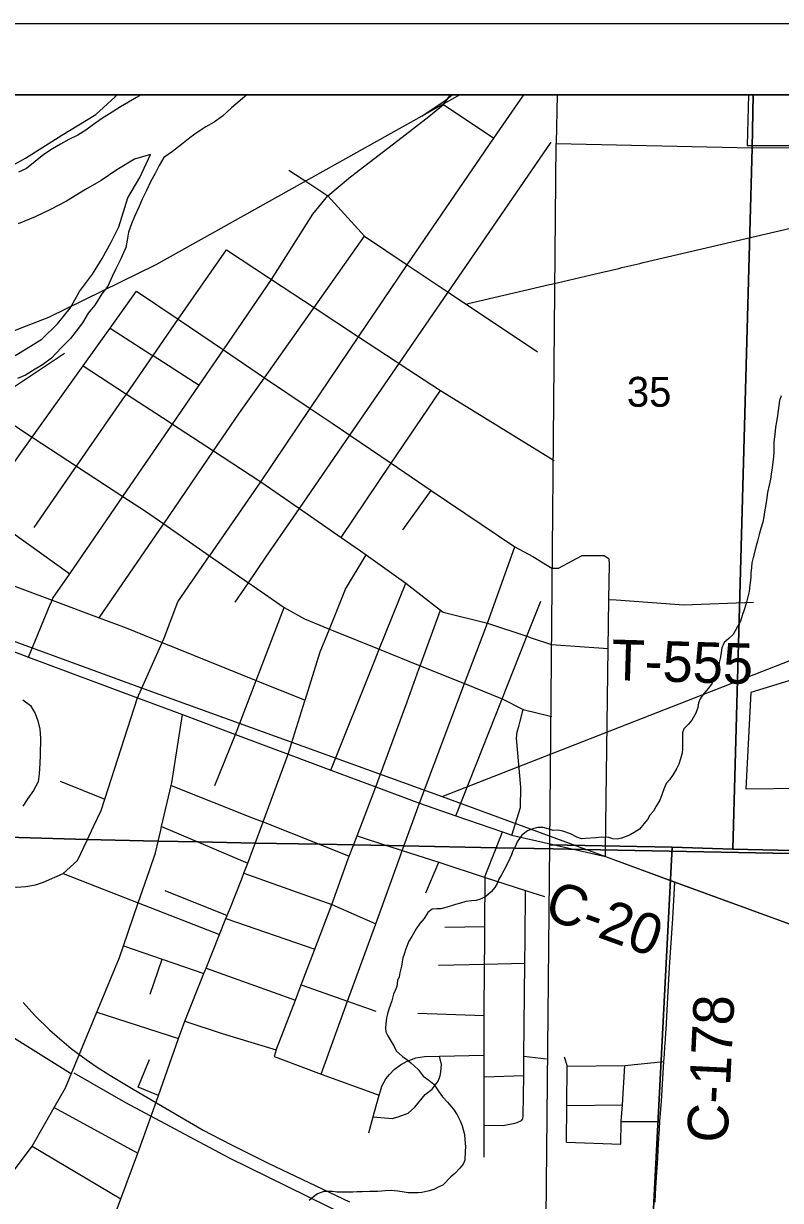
# Model space of a CAD drawing. Extents: x 36.7 to 70.7, y 0 to 22.
# Drawn here: x 39.365 to 40.424, y 19.349 to 20.997 of the extents above; entities that cross this region are included whole.
import ezdxf

# ---------------------------------------------------------------- set-up
doc = ezdxf.new("R2010")
doc.units = 0
for name, color, linetype in [('Default', 7, 'Continuous'), ('GM_X_City_Street', 7, 'Continuous'), ('GM_X_County_Road', 7, 'Continuous'), ('GM_X_County_Road_Text', 7, 'Continuous'), ('GM_X_Major_River', 7, 'Continuous'), ('GM_X_Minor_River', 7, 'Continuous'), ('GM_X_Rail_Line', 7, 'Continuous'), ('GM_X_Section', 7, 'Continuous'), ('GM_X_Section_Text', 7, 'Continuous'), ('GM_X_Township_Road', 7, 'Continuous'), ('GM_X_Township_Road_Text', 7, 'Continuous'), ('SH_Data', 7, 'Continuous')]:
    doc.layers.add(name, color=color, linetype=linetype)

msp = doc.modelspace()

# ---------------------------------------------------------------- linework, layer by layer
at = {"layer": 'Default'}
for points in [[(40.3859, 20.8969), (40.1114, 20.8969), (40.1102, 20.8288), (40.3846, 20.8226)], [(41.3719, 20.8969), (40.3859, 20.8969), (40.3846, 20.8226), (41.3712, 20.8297)]]:
    msp.add_lwpolyline(points, close=True, dxfattribs=at)
for points in [[(40.895, 20.8969), (40.3795, 20.8969), (40.3778, 20.8261), (40.5438, 20.8262)], [(40.5967, 20.1257), (40.3825, 20.0602), (40.3755, 19.9253), (40.4538, 19.9259)]]:
    msp.add_lwpolyline(points, dxfattribs=at)
at = {"layer": 'GM_X_City_Street'}
for p, q in [((39.9525, 20.8834), (40.0231, 20.8366)), ((39.4858, 20.5702), (39.5439, 20.533)), ((39.8955, 20.2878), (39.9353, 20.3431)), ((40.0139, 20.1571), (40.0523, 20.2638)), ((39.6325, 19.9296), (39.6611, 20.0013)), ((39.416, 19.936), (39.4784, 19.9107)), ((39.5711, 19.9298), (39.6862, 19.8841)), ((39.9278, 19.7794), (39.946, 19.8222)), ((39.6731, 19.8068), (39.7963, 19.7629)), ((39.5624, 19.7828), (39.6497, 19.7478)), ((39.7963, 19.7629), (39.8576, 19.7361)), ((39.648, 19.7435), (39.7724, 19.7003)), ((39.9544, 19.7312), (40.0104, 19.7324)), ((39.542, 19.6376), (39.5585, 19.6867)), ((39.6201, 19.6741), (39.7451, 19.6289)), ((39.467, 19.6121), (39.5816, 19.5752)), ((39.9167, 19.611), (40.0095, 19.6077)), ((39.7183, 19.5594), (39.7218, 19.5687)), ((40.0651, 19.5508), (40.0967, 19.547)), ((39.7813, 19.5253), (39.8624, 19.4958)), ((40.0093, 19.5215), (40.0648, 19.5238)), ((39.4076, 19.4786), (39.5245, 19.4148)), ((39.3768, 19.4246), (39.5009, 19.3508))]:
    msp.add_line(p, q, dxfattribs=at)
for points in [[(39.0756, 20.5973), (39.1222, 20.6178), (39.146, 20.6331), (39.1885, 20.674), (39.2532, 20.7387), (39.3059, 20.7744), (39.3672, 20.8085), (39.4182, 20.8408), (39.4659, 20.8697), (39.4929, 20.8944), (39.495, 20.8969)], [(39.7906, 20.7554), (39.8222, 20.7823), (39.8948, 20.838), (39.9321, 20.8665), (39.9525, 20.8834), (39.9624, 20.8969)], [(39.6608, 20.1866), (39.6794, 20.2138), (39.7039, 20.2495), (39.7508, 20.3177), (39.8212, 20.4203), (39.8904, 20.521), (39.9588, 20.6206), (39.9682, 20.6343), (40.1031, 20.8307)], [(39.7359, 20.7914), (39.7639, 20.7735), (39.7906, 20.7554)], [(39.4705, 20.1645), (39.5552, 20.2882), (39.5608, 20.2963), (39.6306, 20.3983), (39.667, 20.4515), (39.702, 20.5009), (39.7715, 20.5992), (39.842, 20.6989)], [(39.3793, 20.2913), (39.4354, 20.3723), (39.4387, 20.3771), (39.5027, 20.4695), (39.5086, 20.478), (39.5459, 20.5318), (39.5811, 20.5827), (39.6486, 20.6802)], [(39.6486, 20.6802), (39.7077, 20.6413), (39.7119, 20.6385), (39.7715, 20.5992), (39.8336, 20.5583), (39.8849, 20.5246)], [(39.2718, 20.2665), (39.305, 20.3151), (39.3385, 20.3641), (39.3767, 20.4176), (39.4481, 20.5176), (39.4858, 20.5702), (39.5229, 20.622)], [(39.5229, 20.622), (39.5811, 20.5827), (39.6443, 20.5399), (39.702, 20.5009), (39.7658, 20.4578), (39.7965, 20.4371), (39.8212, 20.4203), (39.8793, 20.381), (39.9353, 20.3431), (40.0523, 20.2638), (40.0774, 20.2506), (40.1043, 20.2343), (40.1135, 20.2343), (40.1455, 20.2515)], [(39.9847, 20.6033), (40.033, 20.5712), (40.0842, 20.5373)], [(39.3387, 20.4754), (39.3491, 20.4866), (39.4218, 20.5351)], [(39.5439, 20.533), (39.5459, 20.5318), (39.6104, 20.4905)], [(39.8849, 20.5246), (39.8904, 20.521), (39.9482, 20.4829), (40.1076, 20.3851)], [(39.4481, 20.5176), (39.5086, 20.478), (39.5669, 20.44), (39.573, 20.436), (39.6306, 20.3983), (39.6941, 20.3568), (39.6966, 20.3552)], [(39.8092, 20.2773), (39.8793, 20.381), (39.9482, 20.4829)], [(39.3197, 20.4548), (39.3767, 20.4176), (39.3783, 20.4166)], [(39.3783, 20.4166), (39.4387, 20.3771), (39.5036, 20.3347), (39.5355, 20.3139), (39.5608, 20.2963), (39.6251, 20.2516), (39.6794, 20.2138), (39.685, 20.2099), (39.7293, 20.179), (39.7577, 20.163), (39.7928, 20.1488), (39.7976, 20.1469), (39.8626, 20.1206), (39.9199, 20.0974), (39.9819, 20.0724), (40.0324, 20.052), (40.0346, 20.0509), (40.0638, 20.0361), (40.1042, 20.0263)], [(39.2001, 20.39), (39.241, 20.3608), (39.2432, 20.3592), (39.305, 20.3151), (39.3065, 20.314), (39.4292, 20.2264)], [(39.1805, 20.273), (39.2568, 20.2444), (39.4045, 20.1892), (39.4705, 20.1645), (39.5083, 20.1504), (39.5587, 20.13), (39.6901, 20.0769), (39.6928, 20.0758), (39.7587, 20.0492)], [(39.7946, 19.9513), (39.8569, 20.1063), (39.8626, 20.1206), (39.8997, 20.2129)], [(39.6611, 20.0013), (39.6901, 20.0769), (39.7293, 20.179)], [(39.9699, 19.8873), (40.0346, 20.0509), (40.0664, 20.1315), (40.0693, 20.1387), (40.0887, 20.1879)], [(39.8577, 19.9277), (39.9014, 20.0469), (39.9181, 20.0927), (39.9199, 20.0974), (39.9484, 20.1753)], [(40.0139, 20.1571), (40.0693, 20.1387), (40.0751, 20.1367), (40.1037, 20.1272)], [(39.2277, 19.1683), (39.2656, 19.2467), (39.3144, 19.3333), (39.3351, 19.369), (39.3768, 19.4246), (39.4076, 19.4786), (39.4235, 19.5064), (39.467, 19.6121), (39.474, 19.629), (39.4987, 19.6889), (39.5044, 19.7053), (39.5252, 19.7656), (39.5409, 19.8109), (39.5494, 19.8356), (39.5531, 19.8514), (39.5567, 19.867), (39.5579, 19.8722), (39.5711, 19.9298), (39.572, 19.9335), (39.5869, 20.029)], [(40.048, 19.8604), (40.0601, 19.899), (40.0606, 19.9272), (40.0546, 19.996), (40.0557, 20.0047), (40.0579, 20.0123), (40.06, 20.0199), (40.0638, 20.0361)], [(39.7218, 19.5687), (39.7451, 19.6289), (39.7534, 19.6505), (39.7724, 19.7003), (39.7963, 19.7629), (39.8192, 19.8271), (39.8205, 19.8308), (39.8263, 19.846), (39.8315, 19.8593), (39.8577, 19.9277)], [(39.6862, 19.8841), (39.6999, 19.8787), (39.78, 19.8469), (39.8205, 19.8308)], [(39.5579, 19.8722), (39.6097, 19.8502), (39.6785, 19.8211)], [(40.0094, 19.4093), (40.0094, 19.4542), (40.0093, 19.5215), (40.0093, 19.5519), (40.0093, 19.5915), (40.0095, 19.6077), (40.01, 19.6796), (40.0102, 19.7062), (40.0104, 19.7324), (40.011, 19.8011), (40.011, 19.8034), (40.0263, 19.842), (40.0353, 19.8648)], [(39.8315, 19.8593), (39.8757, 19.845), (39.8877, 19.8411), (39.8948, 19.8388), (39.946, 19.8222), (40.011, 19.8011), (40.0674, 19.7828), (40.0938, 19.7742)], [(40.0094, 19.4542), (40.036, 19.4534), (40.0523, 19.4566), (40.0556, 19.4577), (40.0615, 19.4606), (40.0634, 19.463), (40.0642, 19.4664), (40.0648, 19.5238), (40.0651, 19.5508), (40.0664, 19.6811), (40.0667, 19.7136), (40.0674, 19.7828)], [(39.5044, 19.7053), (39.5585, 19.6867), (39.6171, 19.6666)], [(39.9455, 19.6779), (40.01, 19.6796), (40.0664, 19.6811)], [(39.7534, 19.6505), (39.8183, 19.6276), (39.8576, 19.6137)], [(39.848, 19.4432), (39.854, 19.4658), (39.8559, 19.4729), (39.8624, 19.4958), (39.8646, 19.5034), (39.866, 19.5087), (39.8718, 19.5187), (39.8768, 19.5251), (39.8834, 19.5318), (39.8925, 19.5387), (39.9015, 19.5437), (39.9139, 19.5482), (39.9258, 19.5502), (39.9467, 19.5507), (40.0093, 19.5519)], [(39.854, 19.4658), (39.8805, 19.4632), (39.8888, 19.4658), (39.9032, 19.471), (39.9123, 19.4793), (39.9267, 19.4968), (39.9367, 19.5046), (39.9448, 19.5158), (39.9478, 19.523), (39.9489, 19.5286), (39.9495, 19.5388), (39.9467, 19.5507)], [(39.5534, 19.4954), (39.5249, 19.5073), (39.5268, 19.5119), (39.5411, 19.5459)]]:
    msp.add_lwpolyline(points, dxfattribs=at)
at = {"layer": 'GM_X_County_Road'}
for p, q in [((40.1036, 19.8477), (40.1319, 19.8412)), ((39.4202, 19.8065), (39.4677, 19.7879)), ((40.2632, 19.5736), (40.2639, 19.5838)), ((40.2624, 19.5635), (40.2632, 19.5736)), ((40.261, 19.5432), (40.2617, 19.5533)), ((40.2617, 19.5533), (40.2624, 19.5635)), ((39.7242, 19.5471), (39.7813, 19.5253)), ((40.2548, 19.4488), (40.2554, 19.4591)), ((40.2536, 19.4283), (40.2548, 19.4488)), ((40.2525, 19.4078), (40.2536, 19.4283))]:
    msp.add_line(p, q, dxfattribs=at)
for points in [[(39.9014, 20.6589), (40.0231, 20.8366), (40.0649, 20.8969)], [(39.4027, 20.1848), (39.4045, 20.1892), (39.4058, 20.1923), (39.4292, 20.2264), (39.5036, 20.3347), (39.573, 20.436), (39.6104, 20.4905), (39.6443, 20.5399), (39.7119, 20.6385), (39.7697, 20.73), (39.7906, 20.7554)], [(39.7906, 20.7554), (39.842, 20.6989), (39.9014, 20.6589)], [(40.2321, 20.662), (40.5482, 20.7359), (40.5572, 20.738)], [(39.6257, 20.2524), (39.6966, 20.3552), (39.7658, 20.4578), (39.8336, 20.5583), (39.9014, 20.6589)], [(39.9014, 20.6589), (39.9588, 20.6206), (39.9847, 20.6033), (39.9858, 20.604)], [(40.163, 20.6458), (40.198, 20.654), (40.202, 20.655)], [(40.202, 20.655), (40.2272, 20.6608), (40.2321, 20.662)], [(40.1037, 20.632), (40.1591, 20.6449), (40.163, 20.6458)], [(39.9858, 20.604), (39.9869, 20.6047), (40.1007, 20.6313), (40.1037, 20.632)], [(39.6966, 20.3552), (39.7508, 20.3177), (39.8092, 20.2773), (39.8365, 20.2583)], [(39.5609, 20.135), (39.5621, 20.1377), (39.5804, 20.1868), (39.6251, 20.2516), (39.6257, 20.2524)], [(39.7352, 19.9735), (39.7585, 20.0484), (39.7587, 20.0492), (39.7797, 20.1168), (39.7928, 20.1488), (39.8155, 20.2047), (39.8444, 20.2529)], [(39.8365, 20.2583), (39.8444, 20.2529), (39.877, 20.2293), (39.8997, 20.2129), (39.9484, 20.1753), (39.952, 20.1725), (40.0139, 20.1571)], [(39.1685, 20.1856), (39.2162, 20.1677), (39.299, 20.1368), (39.3715, 20.1096)], [(39.3715, 20.1096), (39.402, 20.1831), (39.4027, 20.1848)], [(39.9187, 19.9049), (39.9819, 20.0724), (40.0139, 20.1571)], [(39.4779, 19.9092), (39.4784, 19.9107), (39.5243, 20.0525), (39.5587, 20.13), (39.5609, 20.135)], [(39.3715, 20.1096), (39.5243, 20.0525), (39.5869, 20.029), (39.6611, 20.0013), (39.7352, 19.9735), (39.7946, 19.9513), (39.8577, 19.9277), (39.9187, 19.9049), (39.9699, 19.8873), (40.0353, 19.8648), (40.048, 19.8604), (40.1036, 19.8477)], [(39.6863, 19.8423), (39.6887, 19.8487), (39.6999, 19.8787), (39.7352, 19.9735)], [(39.4626, 19.8723), (39.4732, 19.8949), (39.4779, 19.9092)], [(39.8918, 19.8305), (39.8948, 19.8388), (39.8969, 19.8446), (39.9187, 19.9049)], [(39.4202, 19.8065), (39.4402, 19.8248), (39.4536, 19.8533), (39.4626, 19.8723)], [(39.1936, 19.8465), (39.3308, 19.7914), (39.3464, 19.7876), (39.355, 19.7873), (39.3678, 19.7882), (39.3812, 19.7907), (39.3925, 19.7942), (39.4202, 19.8065)], [(39.6541, 19.7587), (39.6702, 19.799), (39.6731, 19.8068), (39.6785, 19.8211), (39.6863, 19.8423)], [(39.7813, 19.5253), (39.8183, 19.6276), (39.8576, 19.7361), (39.8918, 19.8305)], [(40.1319, 19.8412), (40.1791, 19.8304), (40.2761, 19.7943)], [(39.4677, 19.7879), (39.5252, 19.7656), (39.639, 19.7212)], [(40.2661, 19.624), (40.2689, 19.6751), (40.2735, 19.7434), (40.2761, 19.7943)], [(40.2761, 19.7943), (40.6359, 19.663), (40.6688, 19.6508)], [(39.5904, 19.5999), (39.6171, 19.6666), (39.6201, 19.6741), (39.639, 19.7212), (39.648, 19.7435), (39.6497, 19.7478), (39.6515, 19.7523), (39.6541, 19.7587)], [(40.2639, 19.5838), (40.2642, 19.5878), (40.2661, 19.624)], [(39.4349, 19.1716), (39.5009, 19.3508), (39.5245, 19.4148), (39.5326, 19.4368), (39.5534, 19.4954), (39.5816, 19.5752), (39.5904, 19.5999)], [(39.5904, 19.5999), (39.6428, 19.5822), (39.7183, 19.5594), (39.7156, 19.5504), (39.7242, 19.5471)], [(40.2554, 19.4591), (40.2578, 19.4874), (40.261, 19.5432)], [(40.2499, 19.3665), (40.2513, 19.3873), (40.2525, 19.4078)], [(40.2487, 19.3463), (40.2492, 19.3572), (40.2499, 19.3665)]]:
    msp.add_lwpolyline(points, dxfattribs=at)
at = {"layer": 'GM_X_Major_River'}
for points in [[(39.6773, 20.8969), (39.6559, 20.8789), (39.6433, 20.8673), (39.6314, 20.8587), (39.62, 20.8524), (39.6077, 20.8442), (39.5974, 20.8367), (39.5859, 20.8277), (39.5733, 20.8176), (39.5611, 20.8094), (39.5545, 20.798), (39.549, 20.7867), (39.5428, 20.7761), (39.5366, 20.7633), (39.5308, 20.7508), (39.5261, 20.7399), (39.5199, 20.7267), (39.5156, 20.7164), (39.5113, 20.7047), (39.5097, 20.6937), (39.5076, 20.6831), (39.501, 20.6676), (39.494, 20.6533), (39.4886, 20.6427), (39.4828, 20.6291), (39.4743, 20.6182), (39.4643, 20.6027), (39.455, 20.5914), (39.4473, 20.5779), (39.4384, 20.5662), (39.4303, 20.556), (39.4173, 20.5429), (39.4038, 20.5282), (39.3912, 20.5189), (39.3809, 20.5129), (39.3675, 20.5043), (39.3561, 20.4999)], [(39.5291, 20.8969), (39.5226, 20.8933), (39.5115, 20.8869), (39.5004, 20.8802), (39.4886, 20.8728), (39.4737, 20.8634), (39.4626, 20.8556), (39.4519, 20.8477), (39.4404, 20.8406), (39.4278, 20.8343), (39.4164, 20.828), (39.4053, 20.8216), (39.3931, 20.8134), (39.3686, 20.7939), (39.3575, 20.7887)], [(39.5421, 20.8137), (39.5197, 20.8071), (39.4952, 20.7918), (39.4731, 20.7769), (39.4513, 20.7646), (39.4246, 20.7482), (39.4024, 20.7363), (39.3807, 20.7262), (39.357, 20.7162)], [(39.4981, 20.7121), (39.5108, 20.753), (39.5274, 20.7812), (39.5421, 20.8137)], [(39.3443, 20.527), (39.3683, 20.5415), (39.3901, 20.5549), (39.412, 20.5763), (39.4301, 20.5985), (39.4428, 20.6216), (39.4613, 20.6457), (39.4749, 20.6679), (39.4873, 20.6906), (39.4981, 20.7121)], [(39.3635, 20.0499), (39.3744, 20.0419), (39.3807, 20.0304), (39.3844, 20.0201), (39.3873, 20.0087), (39.3883, 19.9962), (39.388, 19.9722), (39.3872, 19.9605), (39.3866, 19.9461), (39.3853, 19.9351), (39.3784, 19.9226), (39.3707, 19.9113), (39.3637, 19.9008)]]:
    msp.add_lwpolyline(points, dxfattribs=at)
at = {"layer": 'GM_X_Minor_River'}
for points in [[(40.4252, 20.4755), (40.4228, 20.4691), (40.4208, 20.4551), (40.4199, 20.4479), (40.4187, 20.4392), (40.4171, 20.4316), (40.4162, 20.4214), (40.415, 20.4111), (40.4148, 20.3959), (40.4143, 20.3899), (40.4127, 20.3747), (40.411, 20.3656), (40.4102, 20.3588), (40.4082, 20.3505), (40.4058, 20.3399), (40.4045, 20.3292), (40.4037, 20.3232), (40.4017, 20.3129), (40.4009, 20.3061), (40.3993, 20.2985), (40.3965, 20.2895), (40.3945, 20.2811), (40.3921, 20.272), (40.3902, 20.2656), (40.3858, 20.249), (40.3842, 20.2418), (40.3834, 20.2349), (40.3829, 20.227), (40.3825, 20.2209), (40.3812, 20.2103), (40.3803, 20.2016), (40.3776, 20.1902), (40.376, 20.1845), (40.3736, 20.1758), (40.3705, 20.1679), (40.3681, 20.1599), (40.3638, 20.1513), (40.358, 20.1411), (40.3519, 20.1354), (40.3454, 20.1298), (40.3423, 20.1226), (40.3406, 20.1128), (40.3398, 20.1075), (40.3386, 20.1018), (40.337, 20.0923), (40.3354, 20.0855), (40.3311, 20.0783), (40.3284, 20.0731), (40.3234, 20.0659), (40.3169, 20.0584), (40.3119, 20.0512), (40.3095, 20.0455), (40.3083, 20.0391), (40.3059, 20.0312), (40.3001, 20.0213), (40.2955, 20.0157), (40.289, 20.0089), (40.287, 20.0033), (40.2869, 19.9866), (40.2872, 19.9809), (40.2867, 19.9756), (40.2844, 19.9672), (40.282, 19.9597), (40.2793, 19.954), (40.2739, 19.9453), (40.2688, 19.9378)], [(40.2688, 19.9378), (40.2642, 19.9325), (40.2607, 19.9246), (40.258, 19.9166), (40.2552, 19.9091), (40.2502, 19.9008), (40.2463, 19.8936), (40.2413, 19.888), (40.2382, 19.8819), (40.2329, 19.8759), (40.2267, 19.8688), (40.2195, 19.8639), (40.2137, 19.8606), (40.208, 19.8583), (40.2015, 19.8561), (40.1958, 19.8547), (40.1894, 19.8551), (40.1837, 19.8571), (40.1742, 19.8572), (40.1655, 19.8565), (40.1511, 19.8555), (40.1458, 19.8552), (40.139, 19.8572), (40.1303, 19.8622), (40.1193, 19.8657), (40.1125, 19.8673), (40.1061, 19.8666), (40.0989, 19.869), (40.0921, 19.871), (40.0845, 19.8707), (40.0788, 19.8696), (40.07, 19.8663), (40.062, 19.8603), (40.0558, 19.8509), (40.0535, 19.8448), (40.0496, 19.8384), (40.0476, 19.8327), (40.0453, 19.8274), (40.0414, 19.8195), (40.0368, 19.8108), (40.0337, 19.8044), (40.0298, 19.7984), (40.0275, 19.7927), (40.0244, 19.7867), (40.019, 19.7806), (40.0117, 19.7743), (40.0044, 19.7705), (39.998, 19.7687), (39.9919, 19.7684), (39.9839, 19.7673), (39.9763, 19.7651), (39.9691, 19.7629), (39.9577, 19.7593), (39.9489, 19.7571), (39.9432, 19.7572), (39.9368, 19.7565), (39.9306, 19.752), (39.9252, 19.7433), (39.9195, 19.7365), (39.9141, 19.729), (39.9083, 19.7184), (39.904, 19.7116), (39.8997, 19.7011), (39.8974, 19.6935), (39.8954, 19.6882), (39.8946, 19.6829), (39.8938, 19.6768), (39.8914, 19.6674), (39.8902, 19.6617), (39.8882, 19.6564), (39.887, 19.648), (39.885, 19.6428), (39.8827, 19.6375), (39.8803, 19.628), (39.876, 19.6167), (39.874, 19.6098), (39.8728, 19.6042), (39.8716, 19.5958), (39.8715, 19.5901), (39.8718, 19.5848), (39.8744, 19.5791), (39.8793, 19.5711), (39.883, 19.565), (39.886, 19.5581), (39.895, 19.5504), (39.901, 19.5462), (39.9066, 19.5412), (39.9168, 19.5319), (39.9239, 19.5228), (39.9321, 19.517), (39.9389, 19.5112), (39.9456, 19.5017), (39.9512, 19.4936), (39.958, 19.4863), (39.9666, 19.4764), (39.9718, 19.4683), (39.9759, 19.4603), (39.9785, 19.4531), (39.9821, 19.4409), (39.9824, 19.4341), (39.9831, 19.4238)], [(39.9831, 19.4238), (39.983, 19.4174), (39.9825, 19.4048), (39.9801, 19.3992), (39.9755, 19.3939), (39.9682, 19.3864), (39.9628, 19.3815), (39.9517, 19.3702), (39.9452, 19.3673), (39.9391, 19.3639), (39.9304, 19.3617), (39.922, 19.3599), (39.9167, 19.3592), (39.903, 19.3594), (39.8974, 19.3602), (39.8887, 19.3618), (39.8792, 19.3623), (39.8708, 19.362), (39.8606, 19.361), (39.8488, 19.3611), (39.8386, 19.3608), (39.8314, 19.3605), (39.8257, 19.3602), (39.8033, 19.3604), (39.7972, 19.3613), (39.7908, 19.3613), (39.7851, 19.361), (39.7763, 19.3577), (39.7706, 19.3536), (39.7645, 19.3483)]]:
    msp.add_lwpolyline(points, dxfattribs=at)
at = {"layer": 'GM_X_Rail_Line'}
msp.add_line((39.9752, 20.8969), (39.9223, 20.8673), dxfattribs=at)
for points in [[(39.9223, 20.8673), (39.9549, 20.8892), (39.9647, 20.8969)], [(39.9505, 19.9142), (40.5737, 20.1578), (40.9777, 20.2985), (41.2372, 20.3864), (41.8047, 20.6015), (42.0399, 20.6949), (42.6066, 20.8969)], [(39.9223, 20.8673), (39.5499, 20.659), (39.3996, 20.5854), (39.3303, 20.5584)], [(39.092, 20.2111), (39.1759, 20.1959), (39.5388, 20.0634), (39.9505, 19.9142)], [(39.9505, 19.9142), (40.2796, 19.7934), (40.742, 19.6245), (41.298, 19.4193), (41.8828, 19.2032), (42.4402, 19.0032), (43.0913, 18.7734), (43.6618, 18.5644), (44.5563, 18.22), (44.9526, 18.0665), (45.405, 17.9057), (45.5934, 17.8393)], [(39.0447, 19.7607), (39.1088, 19.7275), (39.2804, 19.6203), (39.4303, 19.527)], [(39.3639, 19.6258), (39.3806, 19.6077), (39.401, 19.5877), (39.4117, 19.578), (39.4314, 19.5615), (39.4522, 19.546), (39.4662, 19.5361), (39.4855, 19.5241), (39.5181, 19.5046), (39.6161, 19.4471), (39.6396, 19.4348), (39.6587, 19.4251), (39.7069, 19.401), (39.8211, 19.3465)], [(39.4351, 19.5275), (39.5072, 19.4857), (39.6526, 19.4084), (39.8435, 19.3143), (39.9823, 19.2538), (40.1053, 19.2054), (40.2394, 19.1588), (40.707, 19.0117), (41.5752, 18.749), (42.4154, 18.492), (43.2547, 18.2349), (44.5058, 17.8517), (44.9515, 17.7199), (45.506, 17.5551), (45.5934, 17.5283)]]:
    msp.add_lwpolyline(points, dxfattribs=at)
at = {"layer": 'GM_X_Section'}
for points in [[(40.3846, 20.8226), (40.3573, 19.8404), (40.2724, 19.8432), (40.1015, 19.8465), (40.1102, 20.8288)], [(41.3712, 20.8297), (41.3719, 20.8169), (41.3623, 19.8182), (40.3573, 19.8404), (40.3846, 20.8226)], [(40.2724, 19.8432), (40.2272, 18.9664), (39.1808, 18.9672), (39.181, 19.1756), (40.0948, 19.1814), (40.1015, 19.8465)], [(40.2724, 19.8432), (40.3573, 19.8404), (41.3623, 19.8182), (41.3264, 18.9176), (41.3255, 18.8876), (40.2272, 18.9664)]]:
    msp.add_lwpolyline(points, close=True, dxfattribs=at)
at = {"layer": 'GM_X_Township_Road'}
for p, q in [((40.1838, 20.1904), (40.1944, 20.1896)), ((40.1037, 20.1272), (40.183, 20.1215)), ((40.1791, 19.8304), (40.1792, 19.8404)), ((40.1249, 19.4815), (40.2032, 19.4823)), ((40.2011, 19.459), (40.2554, 19.4591)), ((40.1246, 19.4303), (40.2007, 19.4275))]:
    msp.add_line(p, q, dxfattribs=at)
for points in [[(41.3748, 20.8969), (38.7934, 20.8969), (38.7934, 19.8608), (38.8465, 19.8607), (38.9071, 19.8613), (38.9743, 19.8619), (39.0385, 19.8625), (39.0949, 19.8611), (39.1212, 19.8604), (39.1666, 19.8625), (39.4534, 19.8539), (39.5528, 19.8519), (39.6095, 19.8508), (39.6885, 19.8492), (39.7798, 19.8474), (39.8261, 19.8465), (39.8755, 19.8455), (39.8966, 19.8451), (40.026, 19.8426), (40.1059, 19.841), (40.1721, 19.8397), (40.7272, 19.8287)], [(40.1792, 19.8404), (40.183, 20.1215), (40.1838, 20.1904), (40.185, 20.2398), (40.1845, 20.2469), (40.1774, 20.2514), (40.159, 20.2516), (40.1455, 20.2515)], [(40.1944, 20.1896), (40.2889, 20.1827), (40.3865, 20.1867)], [(40.7272, 19.8287), (40.1721, 19.8397), (40.1059, 19.841), (40.026, 19.8426), (39.8966, 19.8451), (39.8755, 19.8455), (39.8261, 19.8465), (39.7798, 19.8474), (39.6885, 19.8492), (39.6095, 19.8508), (39.5528, 19.8519), (39.4534, 19.8539), (39.1666, 19.8625), (39.1212, 19.8604), (39.0949, 19.8611), (39.0385, 19.8625), (38.9743, 19.8619), (38.9071, 19.8613), (38.8465, 19.8607), (38.7934, 19.8608), (38.7934, 14.0969)], [(40.1214, 19.5495), (40.1257, 19.5367), (40.2063, 19.5376), (40.261, 19.5432)], [(40.1246, 19.4303), (40.1249, 19.4815), (40.1257, 19.5367)], [(40.2007, 19.4275), (40.2011, 19.459), (40.2032, 19.4823), (40.2063, 19.5376)]]:
    msp.add_lwpolyline(points, dxfattribs=at)
at = {"layer": 'SH_Data'}
for p, q in [((38.6934, 20.9969), (45.6934, 20.9969)), ((38.7934, 20.8969), (45.5934, 20.8969))]:
    msp.add_line(p, q, dxfattribs=at)

# ---------------------------------------------------------------- texts
at = {"layer": 'GM_X_County_Road_Text'}
for s, rotation, p in [('C-20', 340.1025, (40.0908, 19.7452)), ('C-178', 87.2485, (40.3499, 19.4284))]:
    msp.add_text(s, height=0.05682, rotation=rotation, dxfattribs=at).set_placement(p)
at = {"layer": 'GM_X_Section_Text'}
msp.add_text('35', height=0.04186, rotation=0, dxfattribs=at).set_placement((40.2092, 20.4602))
at = {"layer": 'GM_X_Township_Road_Text'}
msp.add_text('T-555', height=0.05682, rotation=358.3152, dxfattribs=at).set_placement((40.1868, 20.0775))

doc.saveas('drawing.dxf')
